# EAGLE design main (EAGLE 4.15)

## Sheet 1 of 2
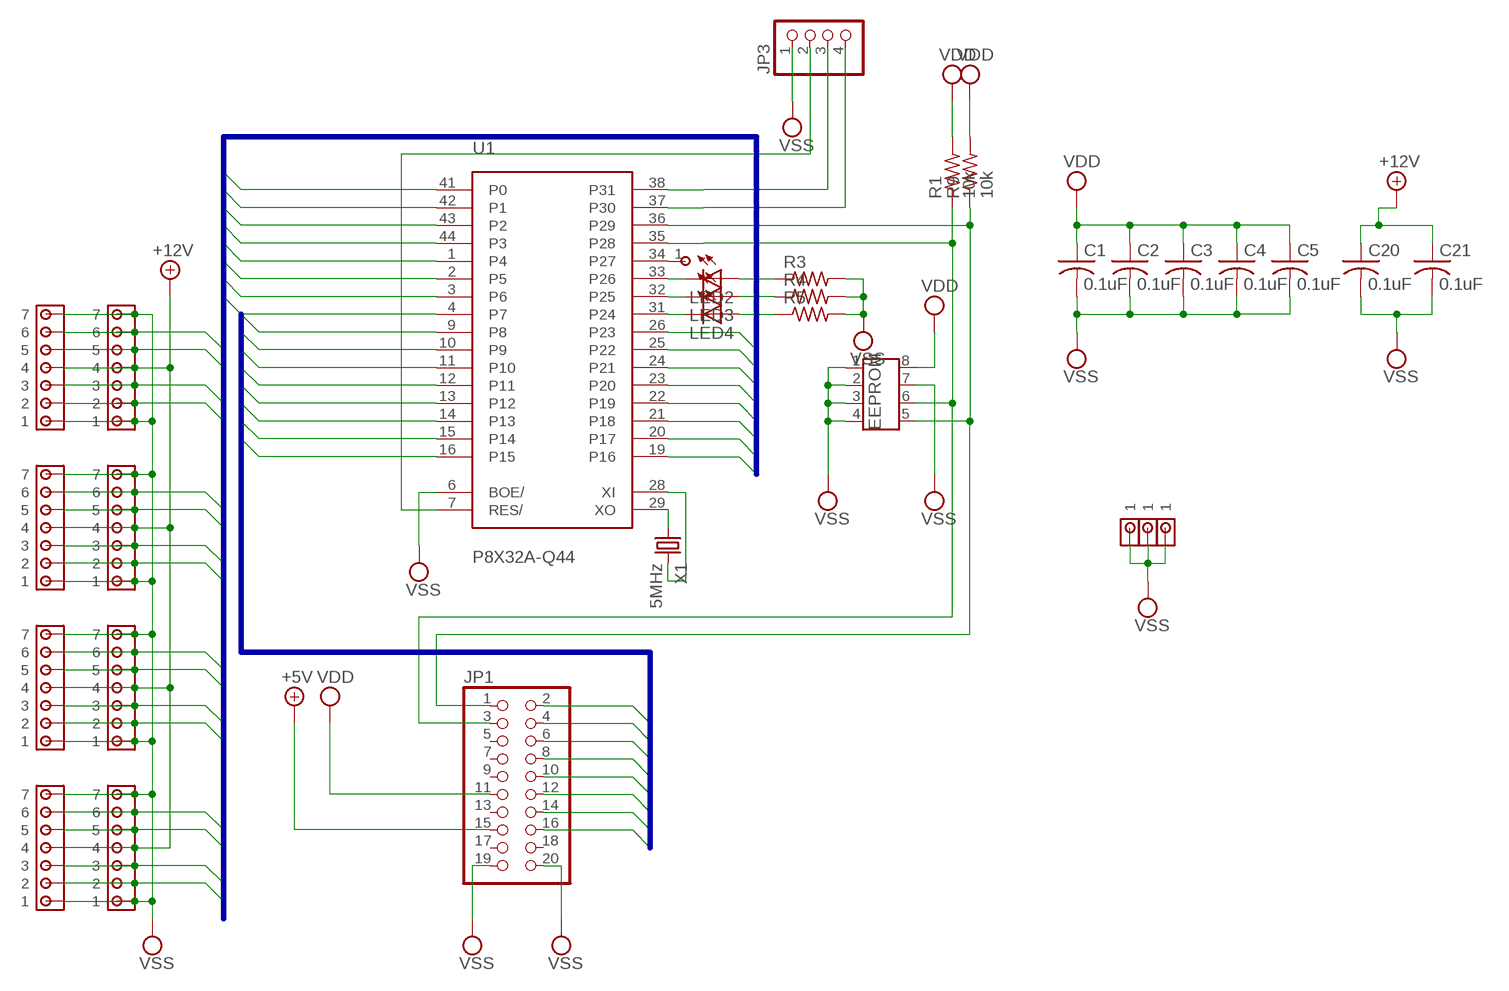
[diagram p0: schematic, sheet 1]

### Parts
C1  0.1uF  C-USC0603  [C0603]
C2  0.1uF  C-USC0603  [C0603]
C3  0.1uF  C-USC0603  [C0603]
C4  0.1uF  C-USC0603  [C0603]
C5  0.1uF  C-USC0603  [C0603]
C20  0.1uF  C-USC0603  [C0603]
C21  0.1uF  C-USC0603  [C0603]
EEPROM  TSSOP8  [TSSOP8]
J1A  SMH-107-02-T-S  [SMH-107]
J1B  SMH-107-02-T-S  [SMH-107]
J2A  SMH-107-02-T-S  [SMH-107]
J2B  SMH-107-02-T-S  [SMH-107]
J3A  SMH-107-02-T-S  [SMH-107]
J3B  SMH-107-02-T-S  [SMH-107]
J4A  SMH-107-02-T-S  [SMH-107]
J4B  SMH-107-02-T-S  [SMH-107]
JP1  PINHD-2X10  [2X10]
JP3  PINHD-1X4N  [1X4N]
LED2  LEDCHIPLED_0603  [CHIPLED_0603]
LED3  LEDCHIPLED_0603  [CHIPLED_0603]
LED4  LEDCHIPLED_0603  [CHIPLED_0603]
R1  10k  R-US_R0603  [R0603]
R3  R-US_R0603  [R0603]
R4  R-US_R0603  [R0603]
R5  R-US_R0603  [R0603]
R9  10k  R-US_R0603  [R0603]
U1  P8X32A-Q44  [P8X32A-Q44]
U$3  TESTPOINT  [TESTPOINT]
U$4  STAND  [STAND4X40]
U$5  STAND  [STAND4X40]
U$6  STAND  [STAND4X40]
X1  5MHz  CRYTALHC49UP  [HC49UP]

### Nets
+5V: JP1.15 ; also sheet 2
+12V: C20.1 C21.1 J1A.4 J1B.4 J2A.4 J2B.4 J3A.4 J3B.4 J4A.4 J4B.4 ; also sheet 2
BUS0: J1A.6 J1B.6 U1.41(P0)
BUS1: J1A.5 J1B.5 U1.42(P1)
BUS2: J1A.3 J1B.3 U1.43(P2)
BUS3: J1A.2 J1B.2 U1.44(P3)
BUS4: J2A.6 J2B.6 U1.1(P4)
BUS5: J2A.5 J2B.5 U1.2(P5)
BUS6: J2A.3 J2B.3 U1.3(P6)
BUS7: J2A.2 J2B.2 U1.4(P7)
BUS8: J3A.6 J3B.6 U1.19(P16)
BUS9: J3A.5 J3B.5 U1.20(P17)
BUS10: J3A.3 J3B.3 U1.21(P18)
BUS11: J3A.2 J3B.2 U1.22(P19)
BUS12: J4A.6 J4B.6 U1.23(P20)
BUS13: J4A.5 J4B.5 U1.24(P21)
BUS14: J4A.3 J4B.3 U1.25(P22)
BUS15: J4A.2 J4B.2 U1.26(P23)
D0: JP1.2 U1.9(P8)
D1: JP1.4 U1.10(P9)
D2: JP1.6 U1.11(P10)
D3: JP1.8 U1.12(P11)
D4: JP1.10 U1.13(P12)
D5: JP1.12 U1.14(P13)
D6: JP1.14 U1.15(P14)
D7: JP1.16 U1.16(P15)
N$1: LED4.C U1.31(P24)
N$2: U1.34(P27) U$3.1
N$4: LED2.C U1.33(P26)
N$5: LED3.C U1.32(P25)
N$7: LED4.A R5.1
N$8: LED3.A R4.1
N$9: LED2.A R3.1
P28: EEPROM.6 JP1.3 R1.1 U1.35(P28)
P29: EEPROM.5 JP1.1 R9.1 U1.36(P29)
P30: JP3.4 U1.37(P30)
P31: JP3.3 U1.38(P31)
RES: JP3.2 U1.7(RES/)
VDD: C1.1 C2.1 C3.1 C4.1 C5.1 EEPROM.8 JP1.11 R1.2 R9.2 ; also sheet 2
VSS: C1.2 C2.2 C3.2 C4.2 C5.2 C20.2 C21.2 EEPROM.1 EEPROM.2 EEPROM.3 EEPROM.4 EEPROM.7 J1A.1 J1A.7 J1B.1 J1B.7 J2A.1 J2A.7 J2B.1 J2B.7 J3A.1 J3A.7 J3B.1 J3B.7 J4A.1 J4A.7 J4B.1 J4B.7 JP1.19 JP1.20 JP3.1 R3.2 R4.2 R5.2 U1.6(BOE/) U$4.P$1 U$5.P$1 U$6.P$1 ; also sheet 2
XI: U1.28(XI) X1.2
XO: U1.29(XO) X1.1
Unconnected: JP1.5 JP1.7 JP1.9 JP1.13 JP1.17 JP1.18

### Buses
BUS[0..15]
D[0..7]

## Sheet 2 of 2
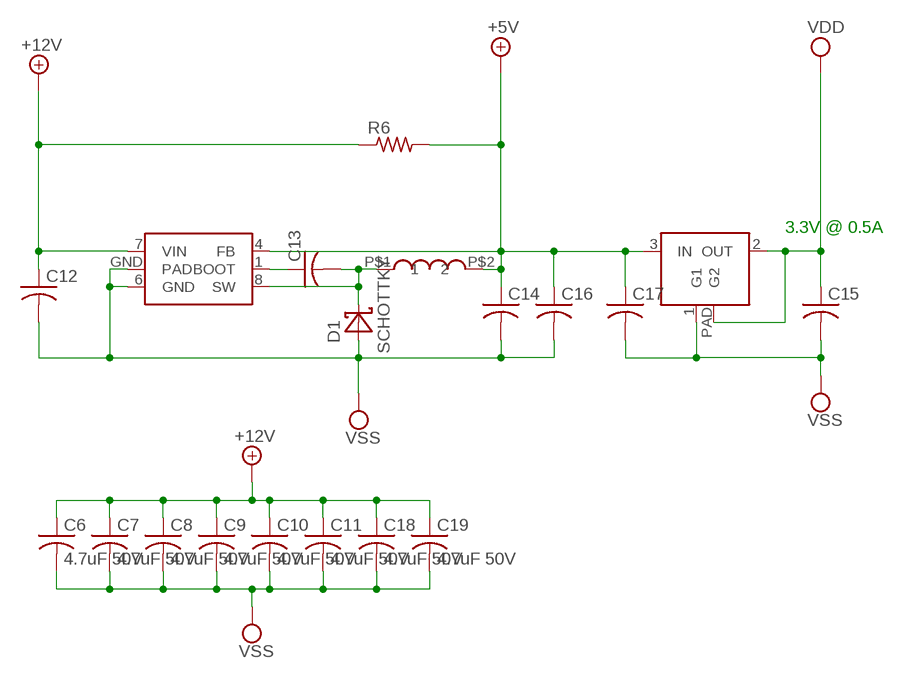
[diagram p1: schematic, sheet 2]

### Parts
C6  4.7uF 50V  C-USC1206  [C1206]
C7  4.7uF 50V  C-USC1206  [C1206]
C8  4.7uF 50V  C-USC1206  [C1206]
C9  4.7uF 50V  C-USC1206  [C1206]
C10  4.7uF 50V  C-USC1206  [C1206]
C11  4.7uF 50V  C-USC1206  [C1206]
C12  C-USC0805  [C0805]
C13  C-USC0603  [C0603]
C14  C-USC1206  [C1206]
C15  C-USC0805  [C0805]
C16  C-USC0805  [C0805]
C17  C-USC0805  [C0805]
C18  4.7uF 50V  C-USC1206  [C1206]
C19  4.7uF 50V  C-USC1206  [C1206]
D1  SCHOTTKY  [SOD123]
I2  744773122  [4.0X4.5]
R6  R-US_R0603  [R0603]
U4  LM22673  [8PSOP]
U5  LM2940GOI  [SOT223]

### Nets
+5V: C14.1 C16.1 C17.1 I2.P$2 R6.2 U4.4(FB) U5.3(IN) ; also sheet 1
+12V: C6.1 C7.1 C8.1 C9.1 C10.1 C11.1 C12.1 C18.1 C19.1 R6.1 U4.7(VIN) ; also sheet 1
N$11: C13.1 U4.1(BOOT)
N$12: C13.2 D1.C I2.P$1 U4.8(SW)
VDD: C15.1 U5.2(OUT) U5.PAD(G2) ; also sheet 1
VSS: C6.2 C7.2 C8.2 C9.2 C10.2 C11.2 C12.2 C14.2 C15.2 C16.2 C17.2 C18.2 C19.2 D1.A U4.6(GND) U4.GND(PAD) U5.1(G1) ; also sheet 1

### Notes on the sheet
- 3.3V @ 0.5A

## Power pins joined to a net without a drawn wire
VDD: U1.8(VDD) U1.18(VDD) U1.30(VDD) U1.40(VDD)
VSS: U1.5(VSS) U1.17(VSS) U1.27(VSS) U1.39(VSS)

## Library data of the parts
C1-C21 = rcl:C-US: CAPACITOR, American symbol
D1 = 000:SCHOTTKY
EEPROM = ref-packages:TSSOP8
I2 = 000:744773122
J1A J1B J2A J2B J3A J3B J4A J4B = 000:SMH-107-02-T-S
JP1 = pinhead:PINHD-2X10: PIN HEADER
JP3 = pinhead:PINHD-1X4: PIN HEADER
LED2-LED4 = led:LED: LED
R1 R3-R6 R9 = rcl:R-US_: RESISTOR, American symbol
U1 = parallax_propeller:P8X32A-Q44
U4 = 000:LM22673
U5 = 000:LM2940
U$3 = matthew_cornelisse:TESTPOINT
U$4-U$6 = 000:STAND
X1 = crystal:CRYTAL: CRYSTAL

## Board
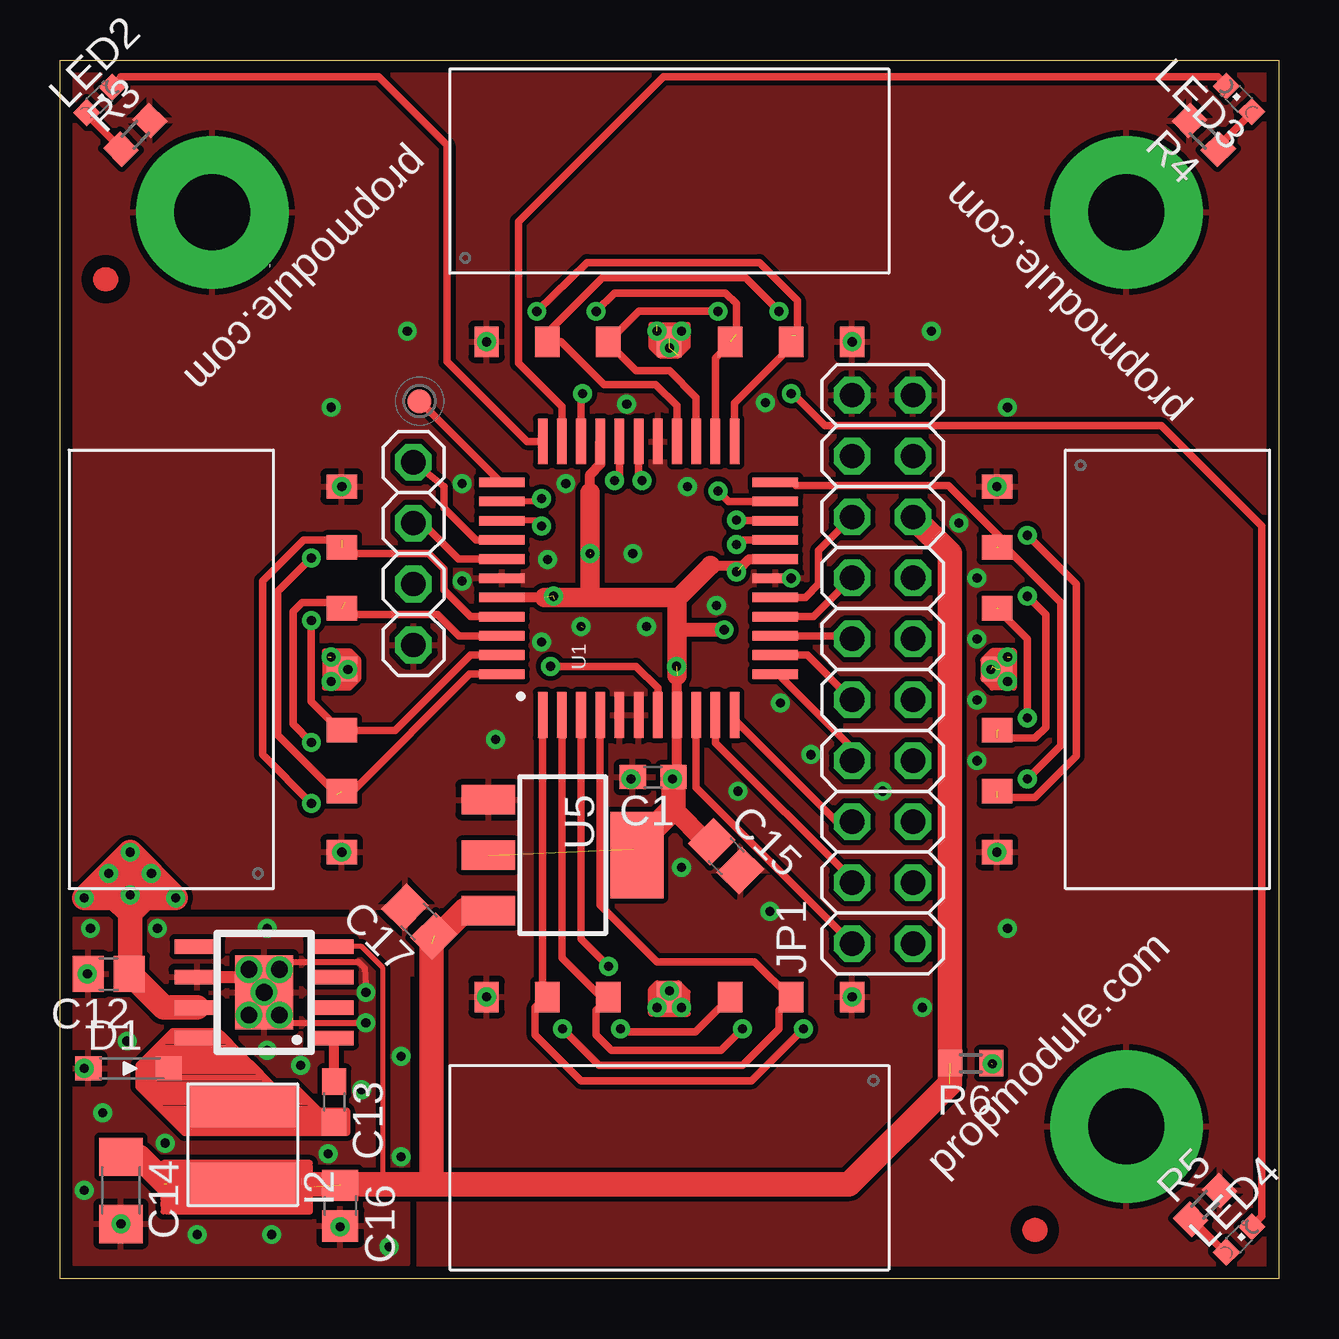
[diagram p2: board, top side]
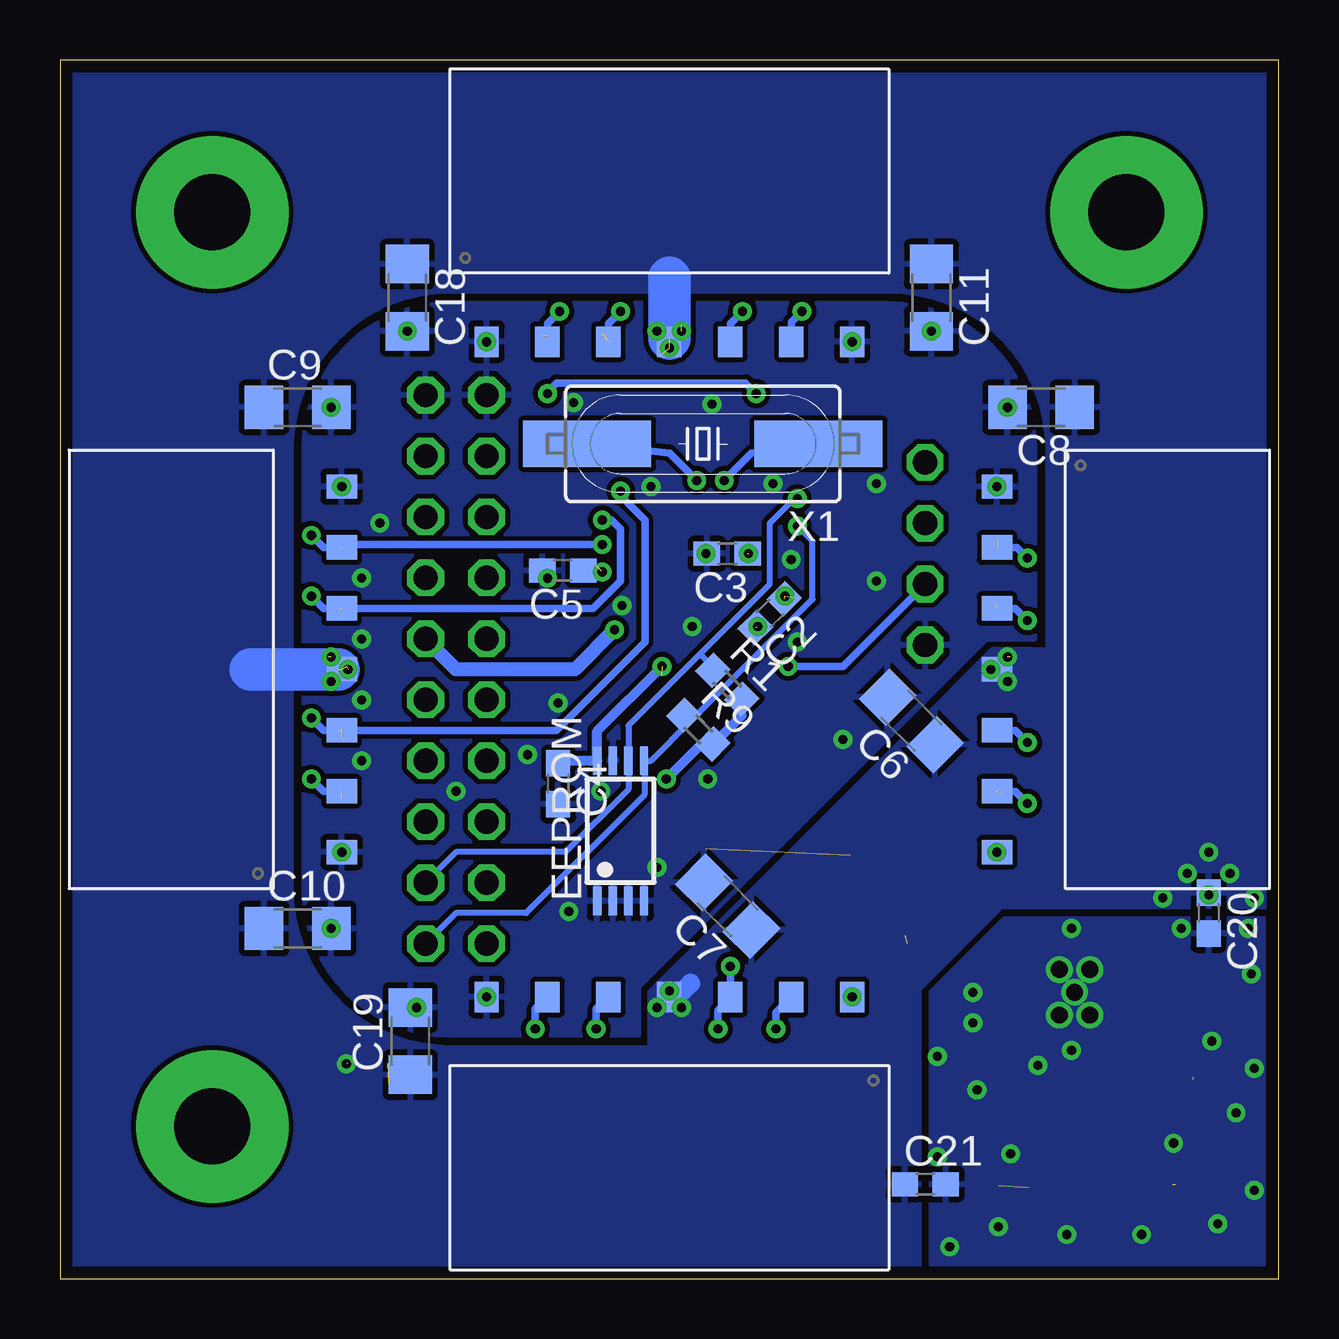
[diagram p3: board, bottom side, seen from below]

Size 50.8 x 50.8 mm. Coordinates in mm from the lower left corner, seen from the top.
Outline: 0,0 0,50.8 50.8,50.8 50.8,0 0,0
Copper layers (1*16): Top 0.035mm / dielectric 1.5mm / Bottom 0.035mm
Design rules "default": minimum track width 7mil, minimum drill 15mil, track to track 8mil, track to pad 8mil, pad to pad 8mil, via to via 8mil, smd to smd 0mil, copper to edge 20mil, drill to drill 8mil, minimum pad ring 10mil, minimum via ring 8mil, stop-mask expansion 4mil, vias tented up to drill 30mil, thermal gap 10mil

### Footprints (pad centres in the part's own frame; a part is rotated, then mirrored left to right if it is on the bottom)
C0603 = smd 1.1 x 1: 1 -0.85,0; 2 0.85,0
C1206 = smd 1.6 x 1.8: 1 -1.4,0; 2 1.4,0
C0805 = smd 1.3 x 1.5: 1 -0.85,0; 2 0.85,0
SOD123 = smd 1.1 x 1: A -1.739,0; C 1.612,0
TSSOP8 = smd 1.2 x 0.35: 1 -2.925,0.975; 2 -2.925,0.325; 3 -2.925,-0.325; 4 -2.925,-0.975; 5 2.925,-0.975; 6 2.925,-0.325; 7 2.925,0.325; 8 2.925,0.975
4.0X4.5 = smd 4.5 x 1.75: P$1 0,1.6; P$2 0,-1.65
SMH-107 = smd 1.27 x 1.016: 1 2.857,-7.62; 2 2.857,-5.08; 3 2.857,-2.54; 4 2.857,0; 5 2.857,2.54; 6 2.857,5.08; 7 2.857,7.62
2X10 = drill 1.016 octagon: 1 -11.43,-1.27; 2 -11.43,1.27; 3 -8.89,-1.27; 4 -8.89,1.27; 5 -6.35,-1.27; 6 -6.35,1.27; 7 -3.81,-1.27; 8 -3.81,1.27; 9 -1.27,-1.27; 10 -1.27,1.27; 11 1.27,-1.27; 12 1.27,1.27; 13 3.81,-1.27; 14 3.81,1.27; 15 6.35,-1.27; 16 6.35,1.27; 17 8.89,-1.27; 18 8.89,1.27; 19 11.43,-1.27; 20 11.43,1.27
1X4N = drill 1.016 octagon: 1 0,5.08; 2 0,2.54; 3 0,0; 4 0,-2.54
CHIPLED_0603 = smd 0.8 x 0.8: A 0,-0.75; C 0,0.75
R0603 = smd 1 x 1.1: 1 -0.85,0; 2 0.85,0
P8X32A-Q44 = smd 1.9 x 0.4: 1 -5.713,4.013; 2 -5.713,3.212; 3 -5.713,2.413; 4 -5.713,1.613; 5 -5.713,0.812; 6 -5.713,0.013; 7 -5.713,-0.787; 8 -5.713,-1.587; 9 -5.713,-2.388; 10 -5.713,-3.188; 11 -5.713,-3.987; 23 5.688,-3.987; 24 5.688,-3.188; 25 5.688,-2.388; 26 5.688,-1.587; 27 5.688,-0.787; 28 5.688,0.013; 29 5.688,0.812; 30 5.688,1.613; 31 5.688,2.413; 32 5.688,3.212; 33 5.688,4.013 | smd 0.4 x 1.9: 12 -4.013,-5.688; 13 -3.212,-5.688; 14 -2.413,-5.688; 15 -1.613,-5.688; 16 -0.812,-5.688; 17 -0.013,-5.688; 18 0.787,-5.688; 19 1.587,-5.688; 20 2.388,-5.688; 21 3.188,-5.688; 22 3.987,-5.688; 34 3.987,5.713; 35 3.188,5.713; 36 2.388,5.713; 37 1.587,5.713; 38 0.787,5.713; 39 -0.013,5.713; 40 -0.812,5.713; 41 -1.613,5.713; 42 -2.413,5.713; 43 -3.212,5.713; 44 -4.013,5.713
8PSOP = smd 0.61 x 1.905: 1 -1.905,-2.781; 2 -0.635,-2.781; 3 0.635,-2.781; 4 1.905,-2.781; 5 1.905,2.781; 6 0.635,2.781; 7 -0.635,2.781; 8 -1.905,2.781 | smd 3.099 x 2.413: GND 0,0
SOT223 = smd 1.219 x 2.235: 1 -2.311,-3.099; 2 0,-3.099; 3 2.311,-3.099 | smd 3.6 x 2.2: PAD 0,3.099
TESTPOINT = smd 1 x 1: 1 0,0
STAND4X40 = drill 3.175 pad 6.35 round: P$1 0,0
HC49UP = smd 5.334 x 1.93: 1 -4.826,0; 2 4.826,0

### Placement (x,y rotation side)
C1  24.72,20.91 180 top
C2  21.21,27.74 225 bottom
C3  22.99,30.23 180 bottom
C4  30.04,20.64 270 bottom
C5  29.84,29.53 180 bottom
C6  15.31,23.25 135 bottom
C7  22.97,15.52 135 bottom
C8  9.91,36.32 180 bottom
C9  40.89,36.32 0 bottom
C10  40.89,14.61 0 bottom
C11  14.48,40.89 270 bottom
C12  2.03,12.7 180 top
C13  11.43,7.37 270 top
C14  2.54,3.68 270 top
C15  27.76,17.61 315 top
C16  11.68,3.05 270 top
C17  14.99,14.89 135 top
C18  36.32,40.89 270 bottom
C19  36.2,9.91 90 bottom
C20  2.92,15.24 270 bottom
C21  14.73,3.94 0 bottom
D1  2.92,8.76 0 top
EEPROM  27.43,18.67 90 bottom
I2  7.62,5.59 0 top
J1A  8.89,25.4 0 top
J1B  8.89,25.4 180 bottom
J2A  25.4,8.89 90 top
J2B  25.4,8.89 90 bottom
J3A  41.91,25.4 180 top
J3B  41.91,25.4 0 bottom
J4A  25.4,41.91 270 top
J4B  25.4,41.91 270 bottom
JP1  34.29,25.4 90 top
JP3  14.73,31.5 180 top
LED2  1.64,49.14 315 top
LED3  49.14,49.18 45 top
LED4  49.15,1.64 315 top
R1  22.99,24.76 315 bottom
R3  3.14,47.68 45 top
R4  47.68,47.68 135 top
R5  47.73,3.08 45 top
R6  37.97,8.98 180 top
R9  24.2,22.89 315 bottom
U1  24.13,29.21 90 top
U4  8.51,11.94 90 top
U5  20.95,17.65 270 top
U$1  [1MM-FIDUCIAL]  1.91,41.66 0 top
U$2  [1MM-FIDUCIAL]  40.64,2.03 0 top
U$3  14.99,36.58 0 top
U$4  6.35,44.45 0 top
U$5  44.45,44.45 0 top
U$6  44.45,6.35 0 top
X1  24,34.8 180 bottom

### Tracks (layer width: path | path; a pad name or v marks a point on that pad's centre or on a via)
+5V  (4 unrouted)
  Top 0.203: U4.4 12.57,13.84 13.46,12.95 13.46,3.94
  Top 0.254: 4.32,3.05 4.32,2.79 | 4.32,3.3 4.32,3.05 | 4.32,3.56 4.32,3.3 | 4.32,3.81 4.32,3.56 | 4.32,4.06 4.32,3.81 | 4.32,4.32 4.32,4.06 | 4.32,4.57 4.32,4.32 | 4.32,4.57 4.32,4.83 10.41,4.83 10.41,4.7 | 10.41,4.7 10.41,4.45 | 10.41,4.45 10.41,4.19 | 10.41,4.19 10.41,3.94 | 10.41,3.94 10.41,3.68 | 10.41,3.68 10.41,3.43 | 10.41,3.43 10.41,3.17 | 10.41,3.17 10.41,2.92 | 10.41,2.92 10.41,2.79 4.45,2.79 4.45,2.92 10.41,2.92 | 10.41,2.92 10.41,3.05 4.32,3.05 | 4.32,3.05 4.32,3.17 10.41,3.17 | 10.41,3.17 10.41,3.3 4.32,3.3 | 4.32,3.3 4.32,3.43 10.41,3.43 | 10.41,3.43 10.41,3.56 4.32,3.56 | 4.32,3.56 4.32,3.68 10.41,3.68 | 10.41,3.68 10.41,3.81 4.32,3.81 | 4.32,3.81 4.32,3.94 I2.P$2 10.41,3.94 | 10.41,3.94 10.41,4.06 4.32,4.06 | 4.32,4.06 4.32,4.19 10.41,4.19 | 10.41,4.19 10.41,4.32 4.32,4.32 | 4.32,4.32 4.32,4.45 10.41,4.45 | 10.41,4.45 10.41,4.57 4.32,4.57 | 4.32,4.57 4.32,4.7 10.41,4.7
  Top 0.406: 13.46,3.94 13.46,3.81
  Top 1.016: 15.49,3.94 13.46,3.94 I2.P$2 | 4.44,3.94 3.3,5.08 C14.1 | 15.49,3.94 15.49,4.57 15.49,13.97 16.89,15.37 17.83,15.37 U5.3 | JP1.15 37.08,30.23 37.08,8.13 32.89,3.94 14.86,3.94 15.49,3.94
+12V  (via drill 0.38)  (14 unrouted)
  Top 0.254: 39.75,26.16 38.86,26.16 38.61,25.91 | 38.61,25.91 38.48,25.78 38.48,25.02 38.86,24.64 39.75,24.64 39.75,26.16 | 39.75,26.16 38.99,26.16 38.86,26.04 | 38.86,26.04 38.73,25.91 | 38.61,25.91 39.62,25.91 39.62,24.89 v39.5,24.89 | v39.5,24.89 38.73,24.89 38.86,24.77 39.62,24.77 39.62,26.04 38.86,26.04 | 38.86,26.04 38.86,25.53 v39.5,24.89 | 24.77,38.73 24.64,38.86 24.64,39.75 24.77,39.75 | 24.77,38.73 25.02,38.48 25.78,38.48 26.16,38.86 26.16,39.75 26.04,39.75 | 25.91,39.75 26.04,39.75 | 24.89,39.75 24.77,39.75 | 24.77,39.75 24.77,38.73 | 24.77,38.73 24.89,38.73 24.89,39.75 | 24.89,39.75 25.91,39.75 | 25.91,39.75 v25.91,39.5 | v25.91,39.5 25.91,38.73 26.04,38.86 26.04,39.75 | 26.04,39.75 26.04,39.62 v25.91,39.5 | 11.05,26.04 11.05,24.64 12.06,24.64 12.45,25.02 12.45,25.78 12.06,26.16 11.05,26.16 11.05,26.04 | 11.05,26.04 12.06,26.04 12.19,25.91 11.18,25.91 11.18,24.89 12.19,24.89 12.06,24.77 11.18,24.77 | 24.89,11.05 24.77,11.05 | 25.91,11.05 26.04,11.05 | 26.04,11.05 26.16,11.05 26.16,11.94 25.78,12.32 24.89,12.32 24.77,12.19 | 24.77,12.19 24.64,12.06 24.64,11.05 24.77,11.05 | 24.77,11.05 24.77,12.19 | 24.77,12.19 24.89,12.19 24.89,11.05 | 24.89,11.05 25.91,11.05 | 25.91,11.05 v25.91,11.3 | v25.91,11.3 25.91,11.94 26.04,11.94 26.04,11.05 | 26.04,11.05 26.04,11.18 v25.91,11.3
  Top 1.016: 2.92,12.7 C12.1 | U4.7 4.32,11.3 2.92,12.7 | 2.92,12.7 2.92,15.11 | 2.92,15.11 v2.92,16 | v1.02,15.88 v2.92,17.78 v4.83,15.88 2.29,15.88 | 2.29,15.88 v1.02,15.88 | v1.02,15.88 2.16,15.88 2.67,16.38 | 2.67,16.38 3.05,16.76 3.43,16.38 2.67,16.38 | 2.92,15.24 2.29,15.88 | 2.92,15.11 2.92,15.24 | 2.92,15.24 3.43,15.75
  Bottom 0.813: v25.4,12 25.08,11.75 24.51,12.32
  Bottom 1.778: 25.4,39.18 25.4,41.72 | 39.18,25.4 42.86,25.4
  other vias: 12,25.4 38.8,25.4 25.4,38.8 2.03,16.89 3.81,16.89 38.86,8.95 24.89,39.5 39.5,25.91 11.3,25.91 11.3,24.89 24.89,11.3
  pour Bottom: 25.15,50.8 0,50.8 0,15.49 11.56,15.49 14.99,12.06 14.99,0 50.8,0 50.8,50.8 25.17,50.8 25.17,41.15 34.54,41.15 arc-90 41.15,34.54 41.15,16.26 arc-90 34.54,9.65 26.23,9.65 26.23,11.94 11.94,26.23 9.65,26.23 9.65,34.67 arc-90 16.26,41.15 25.15,41.15
  pour Bottom (no thermals): 24.13,13.27 24.83,13.34 26.23,11.94 26.23,10.79 24,10.79 24.13,11.75
  pour Bottom (no thermals): 10.29,26.23 11.94,26.23 13.59,24.57 10.48,24.57 10.48,26.1 10.6,26.23
BUS0  (via drill 0.38)  (1 unrouted)
  Top 0.305: U1.41 17.11,27.6 16,28.7 16,29.59 15.37,30.23 12.06,30.23 11.81,30.48 J1A.6 | v10.48,19.81 8.45,21.84 8.45,29.08 10.16,30.8 11.75,30.8
  Bottom 0.305: J1B.6 10.99,20.32 v10.48,19.81
BUS1  (via drill 0.38)  (1 unrouted)
  Top 0.305: U1.42 16.64,26.8 15.75,27.69 11.94,27.69 11.75,27.88 J1A.5 | v10.48,22.35 9.72,23.11 9.72,27.81 10.1,28.19 11.87,28.19
  Bottom 0.305: J1B.5 10.99,22.86 v10.48,22.35
BUS2  (via drill 0.38)
  Top 0.305: U1.43 17.11,26 13.97,22.86 J1A.3 11.68,22.86 10.48,24.07 v10.48,27.43
  Bottom 0.305: J1B.3 10.99,27.94 v10.48,27.43
BUS3  (via drill 0.38)  (1 unrouted)
  Top 0.305: U1.44 17.07,25.2 12.19,20.32 J1A.2 | v10.48,30.04 9.08,28.64 9.08,22.67 11.56,20.19
  Bottom 0.305: J1B.2 10.92,30.48 v10.48,30.04
BUS4  (via drill 0.38)
  Top 0.305: 20.26,11.75 J2A.6 | U1.1 20.12,11.89 20.26,11.75 | 20.26,11.75 19.81,11.3 19.81,10.16 21.72,8.26 28.83,8.26 v30.99,10.41
  Bottom 0.305: J2B.6 30.99,11.24 v30.99,10.41
BUS5  (via drill 0.38)
  Top 0.305: 22.73,11.56 22.86,11.68 J2A.5 | U1.2 20.92,13.37 22.73,11.56 | 22.73,11.56 22.35,11.18 22.35,10.16 22.99,9.53 27.56,9.53 v28.45,10.41
  Bottom 0.305: J2B.5 28.45,11.24 v28.45,10.41
BUS6  (via drill 0.38)
  Top 0.305: U1.3 21.72,14.16 v22.86,13.02 | v23.37,10.41 23.37,10.29 26.48,10.29 J2A.3
  Bottom 0.305: v22.86,13.02 J2B.3 22.86,11.68 23.37,11.18 v23.37,10.41
BUS7  (via drill 0.38)
  Top 0.305: U1.4 22.52,15.58 24.89,13.21 28.96,13.21 30.48,11.68 | 30.48,11.68 J2A.2 | 30.48,11.68 29.97,11.18 29.97,10.41 28.45,8.89 22.48,8.89 v20.95,10.41
  Bottom 0.305: J2B.2 20.95,11.11 v20.95,10.41
BUS8  (via drill 0.38)  (2 unrouted)
  Top 0.305: U1.19 28.38,30.8 v28.19,30.61 | 39.31,20.07 J3A.6 | v40.32,30.99 42.35,28.96 42.35,21.78 40.64,20.07 39.05,20.07
  Bottom 0.305: v28.19,30.61 38.99,30.61 39.12,30.48 39.81,30.48 v40.32,30.99
BUS9  (via drill 0.38)  (2 unrouted)
  Top 0.305: U1.20 28.22,31.6 v28.19,31.62 | v40.32,28.45 41.08,27.69 41.08,22.99 40.64,22.54 39.05,22.54
  Bottom 0.305: v28.19,31.62 27.81,31.62 27.43,31.24 27.43,29.08 28.57,27.94 39.12,27.94 39.81,27.94 v40.32,28.45
BUS10  (via drill 0.38)  (1 unrouted)
  Top 0.305: U1.21 27.86,32.4 v27.43,32.83 | J3A.3 40.32,26.67 v40.32,23.37
  Bottom 0.305: v27.43,32.83 27.43,32.64 26.42,31.62 26.42,26.54 30.1,22.86 39.12,22.86 39.81,22.86 v40.32,23.37
BUS11  (via drill 0.38)
  Top 0.305: U1.22 30.61,33.15 30.68,33.07 37.03,33.07 39.5,30.61 39.05,30.54 J3A.2 39.43,30.48 41.72,28.19 41.72,22.23 v40.32,20.83
  Bottom 0.305: J3B.2 39.81,20.32 v40.32,20.83
BUS12  (via drill 0.38)  (1 unrouted)
  Top 0.305: U1.23 28.12,36.5 30.61,38.99 30.54,39.05 J4A.6 30.48,39.31 | v19.88,40.32 21.97,42.35 29.15,42.35 30.73,40.77 30.73,39.37 30.67,39.31
  Bottom 0.305: J4B.6 20.32,39.88 v19.88,40.32
BUS13  (via drill 0.38)  (1 unrouted)
  Top 0.305: J4A.5 27.94,38.99 27.32,38.37 U1.24 | v22.35,40.32 23.11,41.08 27.75,41.08 28.19,40.64 28.19,39.37
  Bottom 0.305: J4B.5 22.86,39.81 v22.35,40.32
BUS14  (via drill 0.38)
  Top 0.305: U1.25 26.52,36.73 25.4,37.85 24,37.85 22.86,38.99 J4A.3 24.13,40.32 v27.43,40.32
  Bottom 0.305: J4B.3 27.94,39.81 v27.43,40.32
BUS15  (via drill 0.38)
  Top 0.305: U1.26 25.72,36.39 24.83,37.27 22.67,37.27 20.89,39.05 | 20.89,39.05 20.19,39.12 | 20.89,39.05 J4A.2 20.32,39.43 22.61,41.72 28.57,41.72 v29.97,40.32
  Bottom 0.305: J4B.2 30.48,39.81 v29.97,40.32
D0
  Top 0.305: 33.15,13.84 JP1.2 26.52,20.47 U1.9
D1
  Top 0.305: JP1.4 33.15,16.51 27.32,22.34 U1.10
D2
  Top 0.305: JP1.6 33.02,18.92 32.77,18.67 28.12,23.32 U1.11
D3
  Top 0.305: JP1.8 33.02,21.84 33.15,21.97 29.92,25.2 U1.12
D4
  Top 0.305: U1.13 31.15,26 JP1.10
D5
  Top 0.305: U1.14 32.89,26.8 JP1.12
D6
  Top 0.305: U1.15 31.41,27.6 JP1.14
D7
  Top 0.305: U1.16 31.06,28.4 31.62,28.96 31.62,30.35 JP1.16
N$1  (via drill 0.38)
  Top 0.305: v30.48,36.89 30.54,36.89 31.88,35.56 45.91,35.56 50.1,31.37 50.1,2.6 49.67,2.17 | U1.31 21.72,36.7 v21.78,36.89 | 49.67,2.17 49.66,2.16 | LED4.C 49.67,2.17
  Bottom 0.305: v30.48,36.89 30.48,36.96 30.1,37.34 22.23,37.34 v21.78,36.89
N$2
  Top 0.305: U1.34 18.36,33.2 U$3.1
N$4
  Top 0.305: U1.33 19.46,34.9 16.13,38.23 16.13,47.24 13.27,50.1 2.54,50.1 LED2.C
N$5
  Top 0.305: U1.32 20.92,36.36 | 20.92,36.36 20.83,36.45 | 20.92,36.36 19.11,38.16 19.11,44.07 25.15,50.1 48.26,50.1 48.66,49.71 LED3.C
N$7
  Top 0.305: LED4.A 48.61,1.11 48.58,1.08 46.93,2.73 R5.1
N$8
  Top 0.305: LED3.A 49.72,48.65 48.15,47.07 R4.1
N$9
  Top 0.305: 2.7,46.96 2.73,46.93 | R3.1 2.7,46.96 | LED2.A 1.11,48.54 2.7,46.96
N$11
  Top 0.406: U4.1 11.43,10.03 C13.1
N$12  (1 unrouted)
  Top 0.254: 4.95,6.35 11.3,6.35 | 4.7,6.6 11.05,6.6 | 11.05,6.6 11.18,6.6 10.92,6.86 4.45,6.86 4.19,7.11 10.67,7.11 | 10.41,7.37 3.94,7.37 3.68,7.62 7.75,7.62 | 7.75,7.62 10.16,7.62 | 9.91,7.87 3.43,7.87 3.43,8.13 8.76,8.13 | 8.51,8.38 3.56,8.38 | 3.56,8.38 3.56,8.64 8.26,8.64 | 8,8.89 3.56,8.89 3.81,9.14 7.75,9.14 | 7.49,9.4 3.81,9.4 3.94,9.4 4.19,9.65 7.24,9.65 | 4.32,9.91 5.71,9.91 | 5.71,9.91 6.99,9.91 | 4.57,10.16 6.73,10.16 | I2.P$1 7.62,7.49 7.75,7.62 | C13.2 11.14,6.52 11.05,6.6 | 5.71,9.91 5.71,10.03 U4.8 | D1.C 3.68,8.51 3.56,8.38
  Top 0.305: 10.79,6.99 11.94,6.99 11.94,6.1 5.21,6.1 4.95,6.35 4.7,6.6 4.19,7.11 3.68,7.62 3.43,7.87 3.3,8 3.3,8.89 3.81,9.4 4.32,9.91 4.57,10.16 4.7,10.29 6.6,10.29 6.73,10.16 6.99,9.91 7.24,9.65 7.49,9.4 7.75,9.14 8,8.89 8.26,8.64 8.51,8.38 8.76,8.13 8.89,8 9.78,8 9.91,7.87 10.16,7.62 10.41,7.37 10.67,7.11 10.79,6.99
  Top 0.813: 3.63,8.71 3.61,8.71 3.61,8.31
P28  (via drill 0.38)
  Top 0.254: U1.35 19.95,32.4 v20.07,32.51
  Bottom 0.254: v20.07,32.51 20.19,32.51 21.21,31.5 21.21,28.96 24.13,26.04 | JP1.3 34.29,17.78 29.72,17.78 27.11,20.39 EEPROM.6 27.11,23.06 26.8,23.37 | 24.13,26.04 26.8,23.37 | 26.8,23.37 26.92,23.24 | R1.1 23.59,25.49 24.13,26.04
P29  (via drill 0.38)
  Top 0.254: U1.36 19.84,31.6 v20.07,31.37
  Bottom 0.254: v20.07,31.37 19.43,30.73 19.43,28.32 24.51,23.24 | 24.51,23.24 26.16,21.59 26.42,21.59 | JP1.1 34.29,15.24 31.37,15.24 26.42,20.19 26.42,21.59 | 26.42,21.59 EEPROM.5 | R9.1 24.76,23.49 24.51,23.24
P30
  Top 0.305: U1.37 17.34,30.8 16,32.13 16,33.02 JP3.4
P31
  Top 0.305: U1.38 16.61,30 15.24,31.37 JP3.3
RES  (via drill 0.38)
  Top 0.305: U1.7 24.92,24.61 24,25.53 v20.45,25.53
  Bottom 0.305: v20.45,25.53 18.16,25.53 JP3.2
VDD  (via drill 0.38)  (6 unrouted)
  Top 0.406: 22.1,28.4 U1.40 | 22.1,28.4 25.65,28.4 25.65,28.45 25.72,28.45 25.72,27.05 25.72,25.15 U1.8 25.72,20.51 25.78,20.45 25.78,20.57 v25.53,20.83 25.57,20.87 C1.1 | U1.30 22.52,33.95 22.1,33.53 22.1,32.77 v22.1,30.23 22.1,28.4 | U1.18 28.73,30 28.45,29.72 27.11,29.72
  Top 0.584: 25.72,27.05 v27.69,27.05
  Top 0.813: 25.72,25.15 25.72,28.32 25.78,28.38 | 25.78,28.38 27.11,29.72 | 25.78,28.38 22.1,28.38 | 22.1,28.38 20.19,28.38 | 22.1,28.38 22.1,32.77 | 25.57,19.6 25.57,19.57 26.93,18.21 C15.1
  Top 1.016: U5.PAD 24.05,17.73 23.88,17.91 25.57,19.6 C1.1
  Bottom 0.406: C5.1 28.26,29.53 v28.19,29.46 | v25.7,25.53 28.41,22.82 EEPROM.8 30.09,21.59 30.1,21.59 30.04,21.53 C4.1 | 23.59,22.25 23.62,22.23 | 23.59,22.25 R9.2 24.07,22.29 v25.53,20.83 | 23.59,22.25 22.39,23.46 R1.2 22.45,24.16 22.48,24.13 | 23.59,22.25 23.27,22.25
  Bottom 0.584: JP1.11 34.29,25.4 29.34,25.4 v27.69,27.05
  other vias: 20.57,28.45
VSS  (via drill 0.38, 0.7)  (1 unrouted)
  Top 0.254: v12.75,11.94 12.7,12.95 12.45,13.21 8.89,13.21 | 8.64,10.67 v12.75,10.67
  Top 0.508: 5.59,12.57 8.38,12.57
  other vias: 8.51,11.94 13.72,1.33 14.22,5.08 11.18,5.21 12.57,7.87 14.22,9.27 8.64,14.61 8.64,9.53 10.03,8.89 2.79,9.91 1.14,12.7 1.02,8.76 1.78,6.92 4.38,5.65 1.02,3.68 8.83,1.84 5.71,1.84 9.14,12.89 7.87,12.89 7.87,10.99 9.14,10.99 11.68,2.16 2.54,2.29 4.06,14.61 1.27,14.61 30.48,29.2 11.75,17.78 11.75,33.02 17.78,39.05 33.02,39.05 39.05,33.02 39.05,17.78 33.02,11.75 17.78,11.75 36.32,39.5 11.3,36.32 18.16,22.48 25.91,17.14 39.5,14.61 20.32,29.97 21.72,27.18 24.45,27.18 23.88,30.23 27.37,28.07 30.04,24 31.31,21.84 14.48,39.5 39.5,36.32 35.94,11.3 20.07,26.54 16.76,29.08 23.62,36.45 38.23,21.59 38.23,24.13 38.23,26.67 38.23,29.21 37.47,31.5 34.29,20.32 16.76,33.15 21.08,33.15 26.16,33.02 23.8,20.83 28.26,20.32 29.4,36.51 29.59,15.3
  pour Top: 14.48,0.64 0.64,0.64 0.64,14.99 12.19,14.99 12.19,15.49 0,15.49 0,50.8 50.8,50.8 50.8,0 14.99,0 14.99,12.7 14.48,12.7
  pour Bottom: 0.64,14.99 11.43,14.99 14.48,11.94 14.48,0.64 0.64,0.64
  pour Bottom: 10.16,26.67 10.16,34.54 arc-90 16.26,40.64 34.54,40.64 arc-90 40.64,34.54 40.64,16.26 arc-90 34.54,10.16 26.67,10.16 26.67,12.19 12.19,26.67
  pour Top (no thermals): 19.3,34.04 19.3,24.38 28.96,24.38 28.96,34.04
XI  (via drill 0.38)
  Top 0.305: U1.28 24.12,33.41 v24.26,33.27
  Bottom 0.305: X1.2 25.4,34.42 v24.26,33.27
XO  (via drill 0.38)
  Top 0.305: U1.29 23.32,33.48 v23.11,33.27
  Bottom 0.305: X1.1 21.97,34.42 v23.11,33.27

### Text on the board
tPlace: propmodule.com | propmodule.com | propmodule.com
